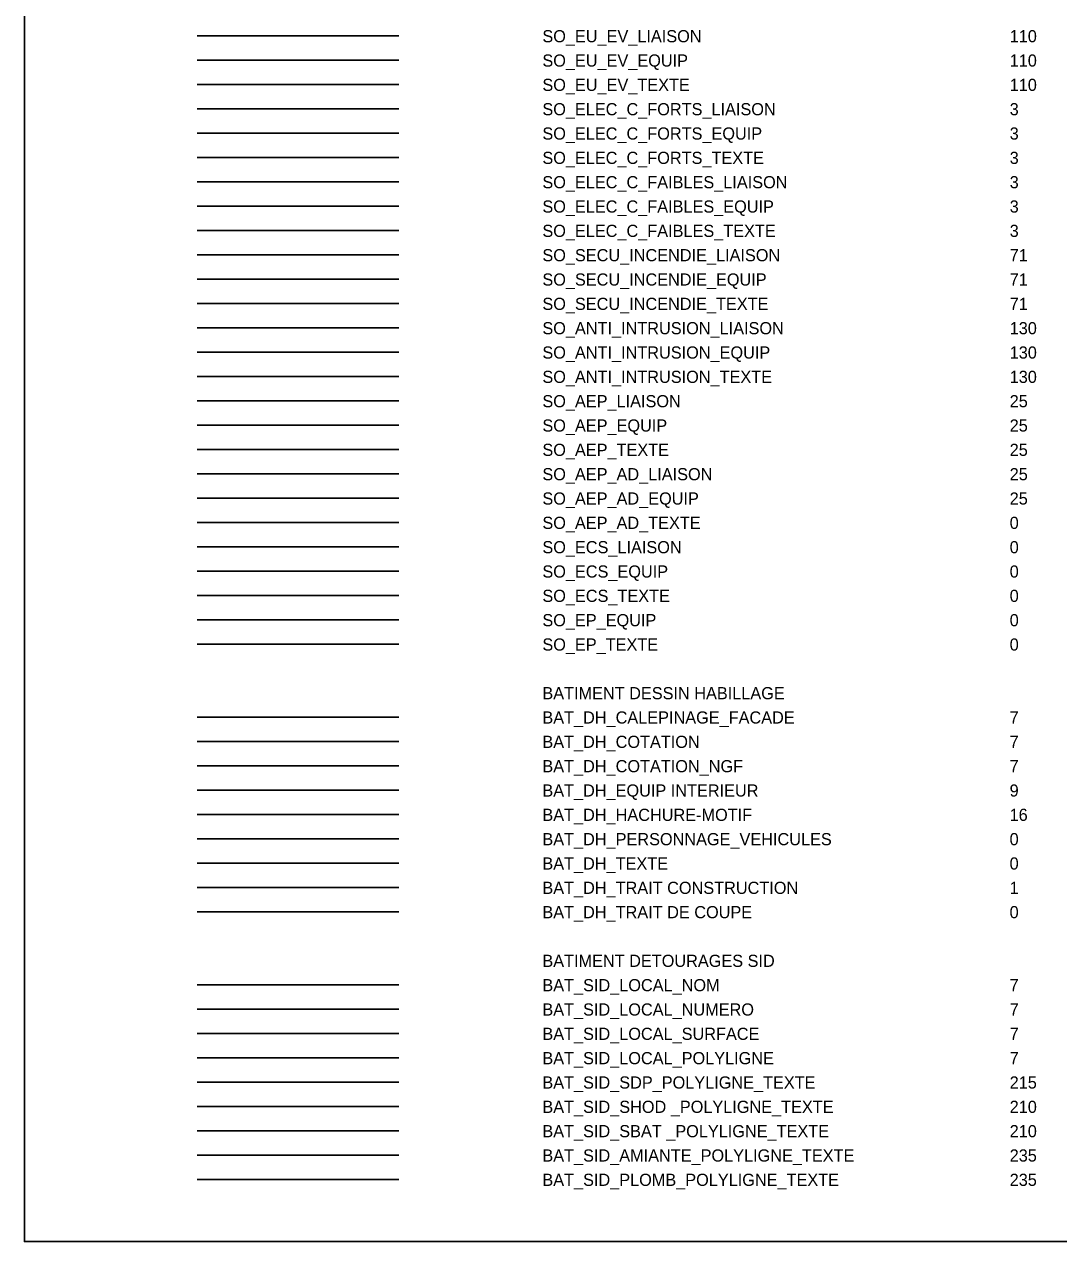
# Model space of a CAD drawing. Extents: x -60 to 214, y -380 to -21.
# Drawn here: x 123.7 to 166.2, y -120.9 to -70.9 of the extents above; entities that cross this region are included whole.
import ezdxf

# ---------------------------------------------------------------- set-up
doc = ezdxf.new("R2010")
doc.units = 0
for name, color, linetype in [('BAT_DH_CALEPINAGE_FACADE', 7, 'Continuous'), ('BAT_DH_COTATION', 7, 'Continuous'), ('BAT_DH_COTATION_NGF', 7, 'Continuous'), ('BAT_DH_EQUIP INTERIEUR', 7, 'Continuous'), ('BAT_DH_HACHURE-MOTIF', 7, 'Continuous'), ('BAT_DH_PERSONNAGE_VEHICULES', 7, 'Continuous'), ('BAT_DH_TEXTE', 7, 'Continuous'), ('BAT_DH_TRAIT CONSTRUCTION', 7, 'Continuous'), ('BAT_DH_TRAIT DE COUPE', 7, 'Continuous'), ('BAT_SID_AMIANTE_POLYLIGNE_TEXTE', 7, 'Continuous'), ('BAT_SID_LOCAL_NOM', 7, 'Continuous'), ('BAT_SID_LOCAL_NUMERO', 7, 'Continuous'), ('BAT_SID_LOCAL_POLYLIGNE', 7, 'Continuous'), ('BAT_SID_LOCAL_SURFACE', 7, 'Continuous'), ('BAT_SID_PLOMB_POLYLIGNE_TEXTE', 7, 'Continuous'), ('BAT_SID_SBAT_POLYLIGNE_TEXTE', 7, 'Continuous'), ('BAT_SID_SDP_POLYLIGNE_TEXTE', 7, 'Continuous'), ('BAT_SID_SHOD_POLYLIGNE_TEXTE', 7, 'Continuous'), ('Default', 7, 'Continuous'), ('DH_TEXTE', 7, 'Continuous'), ('SO_AEP_AD_EQUIP', 7, 'Continuous'), ('SO_AEP_AD_LIAISON', 7, 'Continuous'), ('SO_AEP_AD_TEXTE', 7, 'Continuous'), ('SO_AEP_EQUIP', 7, 'Continuous'), ('SO_AEP_LIAISON', 7, 'Continuous'), ('SO_AEP_TEXTE', 7, 'Continuous'), ('SO_ANTI_INTRUSION_EQUIP', 7, 'Continuous'), ('SO_ANTI_INTRUSION_LIAISON', 7, 'Continuous'), ('SO_ANTI_INTRUSION_TEXTE', 7, 'Continuous'), ('SO_ECS_EQUIP', 7, 'Continuous'), ('SO_ECS_LIAISON', 7, 'Continuous'), ('SO_ECS_TEXTE', 7, 'Continuous'), ('SO_ELEC_C_FAIBLES_EQUIP', 7, 'Continuous'), ('SO_ELEC_C_FAIBLES_LIAISON', 7, 'Continuous'), ('SO_ELEC_C_FAIBLES_TEXTE', 7, 'Continuous'), ('SO_ELEC_C_FORTS_EQUIP', 7, 'Continuous'), ('SO_ELEC_C_FORTS_LIAISON', 7, 'Continuous'), ('SO_ELEC_C_FORTS_TEXTE', 7, 'Continuous'), ('SO_EP_EQUIP', 7, 'Continuous'), ('SO_EP_TEXTE', 7, 'Continuous'), ('SO_EU_EV_EQUIP', 7, 'Continuous'), ('SO_EU_EV_LIAISON', 7, 'Continuous'), ('SO_EU_EV_TEXTE', 7, 'Continuous'), ('SO_SECU_INCENDIE_EQUIP', 7, 'Continuous'), ('SO_SECU_INCENDIE_LIAISON', 7, 'Continuous'), ('SO_SECU_INCENDIE_TEXTE', 7, 'Continuous')]:
    doc.layers.add(name, color=color, linetype=linetype)

msp = doc.modelspace()

# ---------------------------------------------------------------- linework, layer by layer
at = {"layer": 'BAT_DH_CALEPINAGE_FACADE'}
msp.add_line((139.084, -99.345), (130.805, -99.345), dxfattribs=at)
at = {"layer": 'BAT_DH_COTATION'}
msp.add_line((139.084, -100.345), (130.805, -100.345), dxfattribs=at)
at = {"layer": 'BAT_DH_COTATION_NGF'}
msp.add_line((139.084, -101.345), (130.805, -101.345), dxfattribs=at)
at = {"layer": 'BAT_DH_EQUIP INTERIEUR'}
msp.add_line((139.084, -102.345), (130.805, -102.345), dxfattribs=at)
at = {"layer": 'BAT_DH_HACHURE-MOTIF'}
msp.add_line((139.084, -103.345), (130.805, -103.345), dxfattribs=at)
at = {"layer": 'BAT_DH_PERSONNAGE_VEHICULES'}
msp.add_line((139.084, -104.345), (130.805, -104.345), dxfattribs=at)
at = {"layer": 'BAT_DH_TEXTE'}
msp.add_line((139.084, -105.345), (130.805, -105.345), dxfattribs=at)
at = {"layer": 'BAT_DH_TRAIT CONSTRUCTION'}
msp.add_line((139.084, -106.345), (130.805, -106.345), dxfattribs=at)
at = {"layer": 'BAT_DH_TRAIT DE COUPE'}
msp.add_line((139.084, -107.345), (130.805, -107.345), dxfattribs=at)
at = {"layer": 'BAT_SID_AMIANTE_POLYLIGNE_TEXTE'}
msp.add_line((139.084, -117.345), (130.805, -117.345), dxfattribs=at)
at = {"layer": 'BAT_SID_LOCAL_NOM'}
msp.add_line((139.084, -110.345), (130.805, -110.345), dxfattribs=at)
at = {"layer": 'BAT_SID_LOCAL_NUMERO'}
msp.add_line((139.084, -111.345), (130.805, -111.345), dxfattribs=at)
at = {"layer": 'BAT_SID_LOCAL_POLYLIGNE'}
msp.add_line((139.084, -113.345), (130.805, -113.345), dxfattribs=at)
at = {"layer": 'BAT_SID_LOCAL_SURFACE'}
msp.add_line((139.084, -112.345), (130.805, -112.345), dxfattribs=at)
at = {"layer": 'BAT_SID_PLOMB_POLYLIGNE_TEXTE'}
msp.add_line((139.084, -118.345), (130.805, -118.345), dxfattribs=at)
at = {"layer": 'BAT_SID_SBAT_POLYLIGNE_TEXTE'}
msp.add_line((139.084, -116.345), (130.805, -116.345), dxfattribs=at)
at = {"layer": 'BAT_SID_SDP_POLYLIGNE_TEXTE'}
msp.add_line((139.084, -114.345), (130.805, -114.345), dxfattribs=at)
at = {"layer": 'BAT_SID_SHOD_POLYLIGNE_TEXTE'}
msp.add_line((139.084, -115.345), (130.805, -115.345), dxfattribs=at)
at = {"layer": 'Default'}
msp.add_lwpolyline([(208.701, -25.727), (123.7, -25.727), (123.7, -120.902), (208.701, -120.902)], close=True, dxfattribs=at)
at = {"layer": 'SO_AEP_AD_EQUIP'}
msp.add_line((139.084, -90.345), (130.805, -90.345), dxfattribs=at)
at = {"layer": 'SO_AEP_AD_LIAISON'}
msp.add_line((130.805, -89.345), (139.084, -89.345), dxfattribs=at)
at = {"layer": 'SO_AEP_AD_TEXTE'}
msp.add_line((139.084, -91.345), (130.805, -91.345), dxfattribs=at)
at = {"layer": 'SO_AEP_EQUIP'}
msp.add_line((139.084, -87.345), (130.805, -87.345), dxfattribs=at)
at = {"layer": 'SO_AEP_LIAISON'}
msp.add_line((130.805, -86.345), (139.084, -86.345), dxfattribs=at)
at = {"layer": 'SO_AEP_TEXTE'}
msp.add_line((139.084, -88.345), (130.805, -88.345), dxfattribs=at)
at = {"layer": 'SO_ANTI_INTRUSION_EQUIP'}
msp.add_line((139.084, -84.345), (130.805, -84.345), dxfattribs=at)
at = {"layer": 'SO_ANTI_INTRUSION_LIAISON'}
msp.add_line((130.805, -83.345), (139.084, -83.345), dxfattribs=at)
at = {"layer": 'SO_ANTI_INTRUSION_TEXTE'}
msp.add_line((139.084, -85.345), (130.805, -85.345), dxfattribs=at)
at = {"layer": 'SO_ECS_EQUIP'}
msp.add_line((139.084, -93.345), (130.805, -93.345), dxfattribs=at)
at = {"layer": 'SO_ECS_LIAISON'}
msp.add_line((139.084, -92.345), (130.805, -92.345), dxfattribs=at)
at = {"layer": 'SO_ECS_TEXTE'}
msp.add_line((139.084, -94.345), (130.805, -94.345), dxfattribs=at)
at = {"layer": 'SO_ELEC_C_FAIBLES_EQUIP'}
msp.add_line((139.084, -78.345), (130.805, -78.345), dxfattribs=at)
at = {"layer": 'SO_ELEC_C_FAIBLES_LIAISON'}
msp.add_line((130.805, -77.345), (139.084, -77.345), dxfattribs=at)
at = {"layer": 'SO_ELEC_C_FAIBLES_TEXTE'}
msp.add_line((139.084, -79.345), (130.805, -79.345), dxfattribs=at)
at = {"layer": 'SO_ELEC_C_FORTS_EQUIP'}
msp.add_line((139.084, -75.345), (130.805, -75.345), dxfattribs=at)
at = {"layer": 'SO_ELEC_C_FORTS_LIAISON'}
msp.add_line((130.805, -74.345), (139.084, -74.345), dxfattribs=at)
at = {"layer": 'SO_ELEC_C_FORTS_TEXTE'}
msp.add_line((139.084, -76.345), (130.805, -76.345), dxfattribs=at)
at = {"layer": 'SO_EP_EQUIP'}
msp.add_line((139.084, -95.345), (130.805, -95.345), dxfattribs=at)
at = {"layer": 'SO_EP_TEXTE'}
msp.add_line((139.084, -96.345), (130.805, -96.345), dxfattribs=at)
at = {"layer": 'SO_EU_EV_EQUIP'}
msp.add_line((139.084, -72.345), (130.805, -72.345), dxfattribs=at)
at = {"layer": 'SO_EU_EV_LIAISON'}
msp.add_line((130.805, -71.345), (139.084, -71.345), dxfattribs=at)
at = {"layer": 'SO_EU_EV_TEXTE'}
msp.add_line((139.084, -73.345), (130.805, -73.345), dxfattribs=at)
at = {"layer": 'SO_SECU_INCENDIE_EQUIP'}
msp.add_line((139.084, -81.345), (130.805, -81.345), dxfattribs=at)
at = {"layer": 'SO_SECU_INCENDIE_LIAISON'}
msp.add_line((130.805, -80.345), (139.084, -80.345), dxfattribs=at)
at = {"layer": 'SO_SECU_INCENDIE_TEXTE'}
msp.add_line((139.084, -82.345), (130.805, -82.345), dxfattribs=at)

# ---------------------------------------------------------------- texts
at = {"layer": 'BAT_DH_CALEPINAGE_FACADE'}
for s, p in [('BAT_DH_CALEPINAGE_FACADE ', (144.987, -99.61)), ('7 ', (164.186, -99.61))]:
    msp.add_text(s, height=0.5, dxfattribs=at).set_placement(p)
at = {"layer": 'BAT_DH_COTATION'}
for s, p in [('BAT_DH_COTATION ', (144.987, -100.61)), ('7 ', (164.186, -100.61))]:
    msp.add_text(s, height=0.5, dxfattribs=at).set_placement(p)
at = {"layer": 'BAT_DH_COTATION_NGF'}
for s, p in [('BAT_DH_COTATION_NGF ', (144.987, -101.61)), ('7 ', (164.186, -101.61))]:
    msp.add_text(s, height=0.5, dxfattribs=at).set_placement(p)
at = {"layer": 'BAT_DH_EQUIP INTERIEUR'}
for s, p in [('BAT_DH_EQUIP INTERIEUR ', (144.987, -102.61)), ('9 ', (164.186, -102.61))]:
    msp.add_text(s, height=0.5, dxfattribs=at).set_placement(p)
at = {"layer": 'BAT_DH_HACHURE-MOTIF'}
for s, p in [('BAT_DH_HACHURE-MOTIF ', (144.987, -103.61)), ('16 ', (164.186, -103.61))]:
    msp.add_text(s, height=0.5, dxfattribs=at).set_placement(p)
at = {"layer": 'BAT_DH_PERSONNAGE_VEHICULES'}
for s, p in [('BAT_DH_PERSONNAGE_VEHICULES ', (144.987, -104.61)), ('0 ', (164.186, -104.61))]:
    msp.add_text(s, height=0.5, dxfattribs=at).set_placement(p)
at = {"layer": 'BAT_DH_TEXTE'}
for s, p in [('BAT_DH_TEXTE  ', (144.987, -105.61)), ('0 ', (164.186, -105.61))]:
    msp.add_text(s, height=0.5, dxfattribs=at).set_placement(p)
at = {"layer": 'BAT_DH_TRAIT CONSTRUCTION'}
for s, p in [('BAT_DH_TRAIT CONSTRUCTION  ', (144.987, -106.61)), ('1 ', (164.186, -106.61))]:
    msp.add_text(s, height=0.5, dxfattribs=at).set_placement(p)
at = {"layer": 'BAT_DH_TRAIT DE COUPE'}
for s, p in [('BAT_DH_TRAIT DE COUPE ', (144.987, -107.61)), ('0 ', (164.186, -107.61))]:
    msp.add_text(s, height=0.5, dxfattribs=at).set_placement(p)
at = {"layer": 'BAT_SID_AMIANTE_POLYLIGNE_TEXTE'}
for s, p in [('BAT_SID_AMIANTE_POLYLIGNE_TEXTE ', (144.987, -117.61)), ('235 ', (164.189, -117.61))]:
    msp.add_text(s, height=0.5, dxfattribs=at).set_placement(p)
at = {"layer": 'BAT_SID_LOCAL_NOM'}
for s, p in [('BAT_SID_LOCAL_NOM ', (144.987, -110.61)), ('7 ', (164.186, -110.61))]:
    msp.add_text(s, height=0.5, dxfattribs=at).set_placement(p)
at = {"layer": 'BAT_SID_LOCAL_NUMERO'}
for s, p in [('BAT_SID_LOCAL_NUMERO ', (144.987, -111.61)), ('7 ', (164.189, -111.61))]:
    msp.add_text(s, height=0.5, dxfattribs=at).set_placement(p)
at = {"layer": 'BAT_SID_LOCAL_POLYLIGNE'}
for s, p in [('BAT_SID_LOCAL_POLYLIGNE ', (144.987, -113.61)), ('7 ', (164.189, -113.61))]:
    msp.add_text(s, height=0.5, dxfattribs=at).set_placement(p)
at = {"layer": 'BAT_SID_LOCAL_SURFACE'}
for s, p in [('BAT_SID_LOCAL_SURFACE ', (144.987, -112.61)), ('7 ', (164.189, -112.61))]:
    msp.add_text(s, height=0.5, dxfattribs=at).set_placement(p)
at = {"layer": 'BAT_SID_PLOMB_POLYLIGNE_TEXTE'}
for s, p in [('BAT_SID_PLOMB_POLYLIGNE_TEXTE ', (144.987, -118.61)), ('235 ', (164.189, -118.61))]:
    msp.add_text(s, height=0.5, dxfattribs=at).set_placement(p)
at = {"layer": 'BAT_SID_SBAT_POLYLIGNE_TEXTE'}
for s, p in [('BAT_SID_SBAT _POLYLIGNE_TEXTE ', (144.987, -116.61)), ('210 ', (164.189, -116.61))]:
    msp.add_text(s, height=0.5, dxfattribs=at).set_placement(p)
at = {"layer": 'BAT_SID_SDP_POLYLIGNE_TEXTE'}
for s, p in [('BAT_SID_SDP_POLYLIGNE_TEXTE ', (144.987, -114.61)), ('215 ', (164.189, -114.61))]:
    msp.add_text(s, height=0.5, dxfattribs=at).set_placement(p)
at = {"layer": 'BAT_SID_SHOD_POLYLIGNE_TEXTE'}
for s, p in [('BAT_SID_SHOD _POLYLIGNE_TEXTE ', (144.987, -115.61)), ('210 ', (164.189, -115.61))]:
    msp.add_text(s, height=0.5, dxfattribs=at).set_placement(p)
at = {"layer": 'DH_TEXTE'}
for s, p in [('BATIMENT DESSIN HABILLAGE ', (144.987, -98.61)), ('BATIMENT DETOURAGES SID ', (144.987, -109.61))]:
    msp.add_text(s, height=0.5, dxfattribs=at).set_placement(p)
at = {"layer": 'SO_AEP_AD_EQUIP'}
for s, p in [('SO_AEP_AD_EQUIP ', (144.987, -90.61)), ('25 ', (164.189, -90.61))]:
    msp.add_text(s, height=0.5, dxfattribs=at).set_placement(p)
at = {"layer": 'SO_AEP_AD_LIAISON'}
for s, p in [('SO_AEP_AD_LIAISON ', (144.987, -89.61)), ('25 ', (164.189, -89.61))]:
    msp.add_text(s, height=0.5, dxfattribs=at).set_placement(p)
at = {"layer": 'SO_AEP_AD_TEXTE'}
for s, p in [('SO_AEP_AD_TEXTE ', (144.987, -91.61)), ('0', (164.189, -91.61))]:
    msp.add_text(s, height=0.5, dxfattribs=at).set_placement(p)
at = {"layer": 'SO_AEP_EQUIP'}
for s, p in [('SO_AEP_EQUIP ', (144.987, -87.61)), ('25 ', (164.189, -87.61))]:
    msp.add_text(s, height=0.5, dxfattribs=at).set_placement(p)
at = {"layer": 'SO_AEP_LIAISON'}
for s, p in [('SO_AEP_LIAISON ', (144.987, -86.61)), ('25 ', (164.189, -86.61))]:
    msp.add_text(s, height=0.5, dxfattribs=at).set_placement(p)
at = {"layer": 'SO_AEP_TEXTE'}
for s, p in [('SO_AEP_TEXTE ', (144.987, -88.61)), ('25 ', (164.189, -88.61))]:
    msp.add_text(s, height=0.5, dxfattribs=at).set_placement(p)
at = {"layer": 'SO_ANTI_INTRUSION_EQUIP'}
for s, p in [('SO_ANTI_INTRUSION_EQUIP ', (144.987, -84.61)), ('130 ', (164.189, -84.61))]:
    msp.add_text(s, height=0.5, dxfattribs=at).set_placement(p)
at = {"layer": 'SO_ANTI_INTRUSION_LIAISON'}
for s, p in [('SO_ANTI_INTRUSION_LIAISON ', (144.987, -83.61)), ('130 ', (164.189, -83.61))]:
    msp.add_text(s, height=0.5, dxfattribs=at).set_placement(p)
at = {"layer": 'SO_ANTI_INTRUSION_TEXTE'}
for s, p in [('SO_ANTI_INTRUSION_TEXTE ', (144.987, -85.61)), ('130 ', (164.189, -85.61))]:
    msp.add_text(s, height=0.5, dxfattribs=at).set_placement(p)
at = {"layer": 'SO_ECS_EQUIP'}
for s, p in [('SO_ECS_EQUIP ', (144.987, -93.61)), ('0', (164.189, -93.61))]:
    msp.add_text(s, height=0.5, dxfattribs=at).set_placement(p)
at = {"layer": 'SO_ECS_LIAISON'}
for s, p in [('SO_ECS_LIAISON ', (144.987, -92.61)), ('0', (164.189, -92.61))]:
    msp.add_text(s, height=0.5, dxfattribs=at).set_placement(p)
at = {"layer": 'SO_ECS_TEXTE'}
for s, p in [('SO_ECS_TEXTE ', (144.987, -94.61)), ('0', (164.189, -94.61))]:
    msp.add_text(s, height=0.5, dxfattribs=at).set_placement(p)
at = {"layer": 'SO_ELEC_C_FAIBLES_EQUIP'}
for s, p in [('SO_ELEC_C_FAIBLES_EQUIP ', (144.987, -78.61)), ('3 ', (164.189, -78.61))]:
    msp.add_text(s, height=0.5, dxfattribs=at).set_placement(p)
at = {"layer": 'SO_ELEC_C_FAIBLES_LIAISON'}
for s, p in [('SO_ELEC_C_FAIBLES_LIAISON ', (144.987, -77.61)), ('3 ', (164.189, -77.61))]:
    msp.add_text(s, height=0.5, dxfattribs=at).set_placement(p)
at = {"layer": 'SO_ELEC_C_FAIBLES_TEXTE'}
for s, p in [('SO_ELEC_C_FAIBLES_TEXTE ', (144.987, -79.61)), ('3 ', (164.189, -79.61))]:
    msp.add_text(s, height=0.5, dxfattribs=at).set_placement(p)
at = {"layer": 'SO_ELEC_C_FORTS_EQUIP'}
for s, p in [('SO_ELEC_C_FORTS_EQUIP ', (144.987, -75.61)), ('3 ', (164.189, -75.61))]:
    msp.add_text(s, height=0.5, dxfattribs=at).set_placement(p)
at = {"layer": 'SO_ELEC_C_FORTS_LIAISON'}
for s, p in [('SO_ELEC_C_FORTS_LIAISON ', (144.987, -74.61)), ('3 ', (164.189, -74.61))]:
    msp.add_text(s, height=0.5, dxfattribs=at).set_placement(p)
at = {"layer": 'SO_ELEC_C_FORTS_TEXTE'}
for s, p in [('SO_ELEC_C_FORTS_TEXTE ', (144.987, -76.61)), ('3 ', (164.189, -76.61))]:
    msp.add_text(s, height=0.5, dxfattribs=at).set_placement(p)
at = {"layer": 'SO_EP_EQUIP'}
for s, p in [('SO_EP_EQUIP ', (144.987, -95.61)), ('0', (164.189, -95.61))]:
    msp.add_text(s, height=0.5, dxfattribs=at).set_placement(p)
at = {"layer": 'SO_EP_TEXTE'}
for s, p in [('SO_EP_TEXTE ', (144.987, -96.61)), ('0', (164.189, -96.61))]:
    msp.add_text(s, height=0.5, dxfattribs=at).set_placement(p)
at = {"layer": 'SO_EU_EV_EQUIP'}
for s, p in [('SO_EU_EV_EQUIP ', (144.987, -72.61)), ('110 ', (164.189, -72.61))]:
    msp.add_text(s, height=0.5, dxfattribs=at).set_placement(p)
at = {"layer": 'SO_EU_EV_LIAISON'}
for s, p in [('SO_EU_EV_LIAISON ', (144.987, -71.61)), ('110 ', (164.189, -71.61))]:
    msp.add_text(s, height=0.5, dxfattribs=at).set_placement(p)
at = {"layer": 'SO_EU_EV_TEXTE'}
for s, p in [('SO_EU_EV_TEXTE ', (144.987, -73.61)), ('110 ', (164.189, -73.61))]:
    msp.add_text(s, height=0.5, dxfattribs=at).set_placement(p)
at = {"layer": 'SO_SECU_INCENDIE_EQUIP'}
for s, p in [('SO_SECU_INCENDIE_EQUIP ', (144.987, -81.61)), ('71 ', (164.189, -81.61))]:
    msp.add_text(s, height=0.5, dxfattribs=at).set_placement(p)
at = {"layer": 'SO_SECU_INCENDIE_LIAISON'}
for s, p in [('SO_SECU_INCENDIE_LIAISON ', (144.987, -80.61)), ('71 ', (164.189, -80.61))]:
    msp.add_text(s, height=0.5, dxfattribs=at).set_placement(p)
at = {"layer": 'SO_SECU_INCENDIE_TEXTE'}
for s, p in [('SO_SECU_INCENDIE_TEXTE ', (144.987, -82.61)), ('71 ', (164.189, -82.61))]:
    msp.add_text(s, height=0.5, dxfattribs=at).set_placement(p)

doc.saveas('drawing.dxf')
